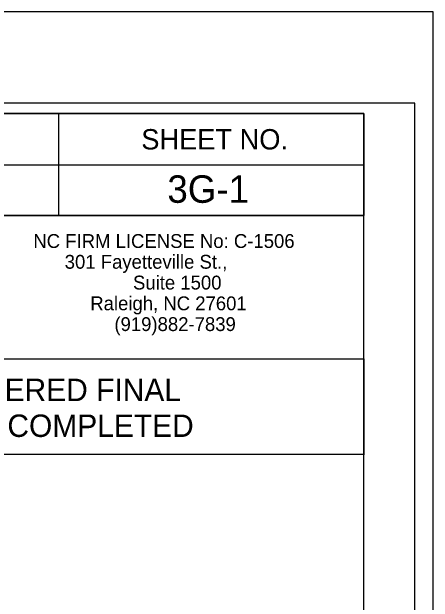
# Model space of a CAD drawing. Extents: x 1298931 to 1298964.7, y 1260171.5 to 1260193.5.
# Drawn here: x 1298962.601 to 1298964.671, y 1260190.576 to 1260193.475 of the extents above; entities that cross this region are included whole.
import ezdxf

# ---------------------------------------------------------------- set-up
doc = ezdxf.new("R2010")
doc.units = 0
for name, color, linetype in [('Default', 7, 'Continuous'), ('Sheet Cutting Line CELL', 7, 'Continuous'), ('Sheet Data Field CELL', 7, 'Continuous'), ('Sheet Plot Border Inside CELL', 7, 'Continuous'), ('Sheet Plot Border Outside CELL', 7, 'Continuous'), ('Sheet Sticker Exception Certification CELL', 7, 'Continuous'), ('Sheet Summary Combination CELL', 7, 'Continuous'), ('Sheet Typical CELL', 7, 'Continuous')]:
    doc.layers.add(name, color=color, linetype=linetype)

msp = doc.modelspace()

# ---------------------------------------------------------------- linework, layer by layer
at = {"layer": 'Sheet Cutting Line CELL'}
msp.add_line((1298964.6711, 1260193.4748), (1298930.9911, 1260193.4748), dxfattribs=at)
at = {"layer": 'Sheet Plot Border Inside CELL'}
msp.add_lwpolyline([(1298964.5811, 1260193.0258), (1298931.2511, 1260193.0258), (1298931.2511, 1260171.9238), (1298964.5811, 1260171.9238)], close=True, dxfattribs=at)
at = {"layer": 'Sheet Plot Border Outside CELL'}
msp.add_lwpolyline([(1298964.6711, 1260193.4748), (1298930.9911, 1260193.4748), (1298930.9911, 1260171.4748), (1298964.6711, 1260171.4748)], close=True, dxfattribs=at)
at = {"layer": 'Sheet Sticker Exception Certification CELL'}
for p, q in [((1298960.3301, 1260191.7702), (1298964.3308, 1260191.7702)), ((1298964.3308, 1260191.77), (1298964.3308, 1260191.3)), ((1298964.3308, 1260191.3002), (1298960.3301, 1260191.3002))]:
    msp.add_line(p, q, dxfattribs=at)
at = {"layer": 'Sheet Summary Combination CELL'}
for p, q in [((1298962.8311, 1260192.9738), (1298962.8311, 1260192.4738)), ((1298960.3301, 1260192.7238), (1298964.3311, 1260192.7238)), ((1298960.3301, 1260192.4738), (1298964.3311, 1260192.4738))]:
    msp.add_line(p, q, dxfattribs=at)
for points in [[(1298964.3311, 1260192.9748), (1298934.3311, 1260192.9748), (1298934.3311, 1260171.9748), (1298964.3311, 1260171.9748)], [(1298960.3301, 1260192.9748), (1298964.3311, 1260192.9748), (1298964.3311, 1260192.4738), (1298960.3301, 1260192.4738)]]:
    msp.add_lwpolyline(points, close=True, dxfattribs=at)
at = {"layer": 'Sheet Typical CELL'}
msp.add_lwpolyline([(1298964.3308, 1260192.4738), (1298960.3301, 1260192.4738), (1298960.3301, 1260191.7702), (1298964.3308, 1260191.7702)], close=True, dxfattribs=at)

# ---------------------------------------------------------------- texts
at = {"layer": 'Default'}
for s, p in [('NC FIRM LICENSE No: C-1506', (1298962.7068, 1260192.3152)), ('301 Fayetteville St., ', (1298962.8609, 1260192.2132)), ('Suite 1500', (1298963.1964, 1260192.1112)), ('Raleigh, NC 27601', (1298962.9865, 1260192.0092)), ('(919)882-7839', (1298963.1049, 1260191.9072))]:
    msp.add_text(s, height=0.068, rotation=360, dxfattribs=at).set_placement(p)
at = {"layer": 'Sheet Data Field CELL'}
msp.add_text('3G-1', height=0.135, dxfattribs=at).set_placement((1298963.3652, 1260192.5368))
at = {"layer": 'Sheet Sticker Exception Certification CELL'}
for s, p in [('DOCUMENT NOT CONSIDERED FINAL', (1298960.7515, 1260191.5633)), ('UNLESS ALL SIGNATURES COMPLETED', (1298960.6501, 1260191.3873))]:
    msp.add_text(s, height=0.11, dxfattribs=at).set_placement(p)
at = {"layer": 'Sheet Summary Combination CELL'}
msp.add_text('SHEET NO.', height=0.1, dxfattribs=at).set_placement((1298963.2371, 1260192.7988))

doc.saveas('drawing.dxf')
